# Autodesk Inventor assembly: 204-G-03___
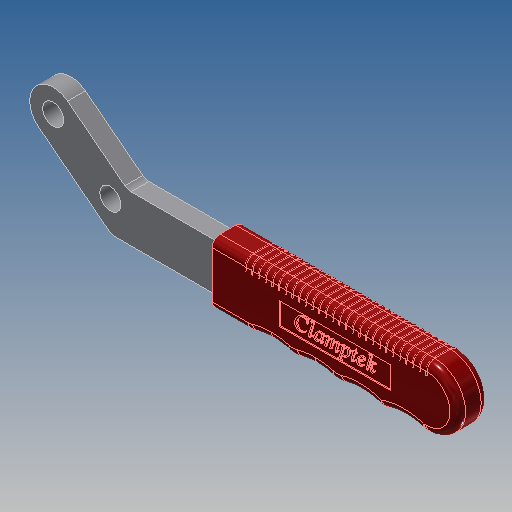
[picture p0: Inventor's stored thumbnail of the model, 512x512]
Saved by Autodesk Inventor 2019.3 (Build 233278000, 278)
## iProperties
Created: 2012-09
Part Number: 204-G-03___
Material: Ogólny
Document SubType Name: Assembly
Designer: CADENGINEERING4
Author: CADENGINEERING4
Revision Number: ÈÎºÎ
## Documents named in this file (3)
- E:\STRONA\Horizontal toggle clamp\CH-204-GBLH\204-G-03___.iam
- E:\STRONA\Horizontal toggle clamp\CH-204-GBLH\204-GB-07___.ipt
- E:\STRONA\Horizontal toggle clamp\CH-204-GBLH\204-GB-03___.ipt
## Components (2 placed, 2 different names)
1. 204-GB-07____23
2. 204-GB-03____24
